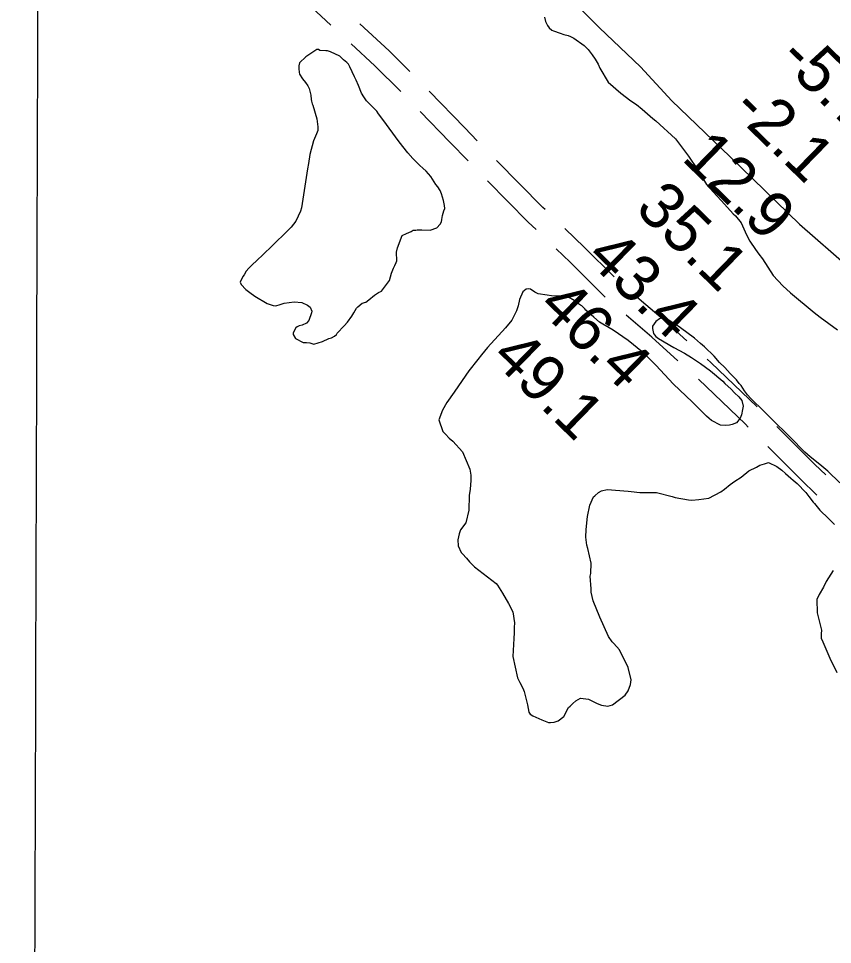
# Model space of a CAD drawing. Extents: x 3146026 to 3183936, y 897894 to 923344.
# Drawn here: x 3171140 to 3172319, y 911149 to 912491 of the extents above; entities that cross this region are included whole.
import ezdxf

# ---------------------------------------------------------------- set-up
doc = ezdxf.new("R2010")
doc.units = 0
for name, color, linetype in [('V-GRID-MAJR', 7, 'Continuous'), ('V-RIVR-EDGE', 7, 'Continuous'), ('V-RIVR-RANG', 7, 'Continuous'), ('V-ROAD-CNTR', 7, 'Continuous'), ('V-SITE-VEGE', 7, 'Continuous')]:
    doc.layers.add(name, color=color, linetype=linetype)

msp = doc.modelspace()

# ---------------------------------------------------------------- linework, layer by layer
at = {"layer": 'V-GRID-MAJR'}
msp.add_spline([(3171139.739, 903307.688), (3171158.249, 909367.4720000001), (3171176.767, 915430.341), (3171195.286, 921493.257), (3171195.295, 921496.294)], degree=3, dxfattribs=at)
at = {"layer": 'V-RIVR-EDGE'}
msp.add_lwpolyline([(3171909.7604397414, 912548.9168714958), (3171981.3681568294, 912477.7493021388), (3172040.717788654, 912421.2860583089), (3172086.204332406, 912371.9958038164), (3172170.4794758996, 912291.2786316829), (3172271.368358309, 912193.0701987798), (3172343.3932618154, 912130.2300927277)], dxfattribs=at)
at = {"layer": 'V-ROAD-CNTR'}
for points in [[(3171592.128481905, 912481.5951567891), (3171563.9692948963, 912507.5982092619), (3171517.5963283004, 912548.2484513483)], [(3171706.8015192, 912414.5415475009), (3171676.527957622, 912444.3772807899), (3171634.3485025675, 912483.4374600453)], [(3171693.725132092, 912385.3080883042), (3171655.8020423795, 912422.6827192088), (3171621.5019880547, 912454.4461990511)], [(3171804.355570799, 912314.137104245), (3171786.404285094, 912332.6700300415), (3171734.8438818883, 912386.0228365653)], [(3171791.0886884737, 912284.714632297), (3171764.8437149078, 912311.8099699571), (3171721.566935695, 912356.5911874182)], [(3171902.5150764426, 912214.3249582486), (3171899.1538444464, 912217.5401821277), (3171832.259361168, 912285.478653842)], [(3171889.552299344, 912185.2094897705), (3171878.0921555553, 912196.1718178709), (3171819.0612445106, 912256.1239945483)], [(3172002.8939126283, 912116.7504908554), (3171959.7979250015, 912159.5304118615), (3171931.4180597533, 912186.6774878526)], [(3171989.789089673, 912087.4880876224), (3171938.8600749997, 912138.0435881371), (3171918.4552912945, 912157.5620111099)], [(3172107.831524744, 912024.1596601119), (3172076.843093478, 912052.1194241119), (3172032.407737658, 912089.7984758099)], [(3172095.073270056, 911995.2646299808), (3172057.0889065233, 912029.5365758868), (3172019.8399865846, 912061.1218744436)], [(3172209.8377936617, 911928.3137008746), (3172142.7588854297, 911992.6459396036), (3172137.529803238, 911997.3639552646)], [(3172196.7876562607, 911899.1104547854), (3172192.7315462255, 911903.1526317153), (3172124.7028001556, 911968.3958154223)], [(3172309.255632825, 911829.749789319), (3172293.5084246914, 911845.075531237), (3172238.2415764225, 911900.1525328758)], [(3172296.2273357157, 911800.5668942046), (3172272.4575753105, 911823.7004687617), (3172225.1201789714, 911870.8752568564)]]:
    msp.add_lwpolyline(points, dxfattribs=at)
at = {"layer": 'V-SITE-VEGE'}
for points in [[(3171901.679000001, 912493.0919999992), (3171903.251000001, 912486.8459999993), (3171905.996000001, 912480.9879999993), (3171908.738000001, 912477.4779999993), (3171912.258000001, 912474.3569999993), (3171914.995000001, 912473.1919999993), (3171924.379000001, 912469.6919999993), (3171929.851000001, 912468.1369999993), (3171936.103000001, 912466.5869999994), (3171939.622000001, 912465.0279999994), (3171944.316000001, 912462.6939999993), (3171959.1780000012, 912452.1689999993), (3171965.052000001, 912446.3199999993), (3171970.923000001, 912438.5169999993), (3171975.230000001, 912432.2729999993), (3171979.541000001, 912424.8589999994), (3171981.895000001, 912419.0019999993), (3171994.041000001, 912398.7059999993), (3172012.430000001, 912383.1129999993), (3172026.906000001, 912371.8079999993), (3172035.118000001, 912366.3519999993), (3172043.335000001, 912359.7239999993), (3172058.594000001, 912346.4679999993), (3172062.897000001, 912342.9589999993), (3172091.463000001, 912316.8309999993), (3172110.259000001, 912291.4709999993), (3172123.184000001, 912272.3479999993), (3172136.504000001, 912250.8849999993), (3172138.853000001, 912247.7619999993), (3172141.594000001, 912245.0319999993), (3172151.379000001, 912234.1099999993), (3172158.424000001, 912227.0919999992), (3172175.254000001, 912208.3689999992)], [(3171688.738000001, 912158.8669999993), (3171695.349000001, 912176.8479999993), (3171701.984000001, 912179.5949999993), (3171708.622000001, 912182.7299999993), (3171711.354000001, 912184.2989999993), (3171715.259000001, 912184.6959999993), (3171717.213000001, 912185.0889999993), (3171724.244000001, 912185.1019999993), (3171735.967000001, 912184.3419999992), (3171745.727000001, 912187.8749999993), (3171750.796000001, 912193.3509999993), (3171752.353000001, 912196.4799999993), (3171753.129000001, 912199.9989999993), (3171753.901000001, 912205.8579999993), (3171755.842000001, 912212.5039999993), (3171757.399000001, 912216.0219999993), (3171757.002000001, 912220.3189999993), (3171755.427000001, 912227.3499999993), (3171752.674000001, 912237.1129999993), (3171750.712000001, 912241.7939999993), (3171747.188000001, 912247.2599999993), (3171744.445000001, 912250.7709999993), (3171741.705000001, 912254.6739999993), (3171739.354000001, 912258.5759999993), (3171737.005000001, 912262.0879999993), (3171730.349000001, 912269.8909999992), (3171725.262000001, 912274.1789999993), (3171720.959000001, 912278.0789999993), (3171710.782000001, 912288.2179999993), (3171703.737000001, 912296.4099999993), (3171691.210000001, 912312.4069999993), (3171667.711000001, 912344.7919999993), (3171661.444000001, 912352.9859999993), (3171658.702000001, 912356.8899999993), (3171643.831000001, 912371.7089999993), (3171639.915000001, 912377.5619999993), (3171636.782000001, 912383.0239999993), (3171632.076000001, 912393.9589999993), (3171628.934000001, 912401.7659999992), (3171626.583000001, 912406.4489999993), (3171619.915000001, 912421.2829999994), (3171617.566000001, 912425.1869999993), (3171615.217000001, 912427.5279999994), (3171610.523000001, 912431.4269999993), (3171605.042000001, 912436.4959999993), (3171591.7490000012, 912443.1129999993), (3171587.450000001, 912444.2759999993), (3171585.105000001, 912444.2739999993), (3171576.509000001, 912445.0419999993), (3171574.160000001, 912446.2089999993), (3171571.819000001, 912446.2049999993), (3171555.818000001, 912435.6309999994), (3171546.848000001, 912427.0199999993), (3171546.074000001, 912422.7209999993), (3171545.691000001, 912418.0309999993), (3171546.0900000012, 912413.3429999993), (3171546.875000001, 912410.6089999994), (3171551.186000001, 912403.9759999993), (3171555.493000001, 912398.5129999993), (3171559.017000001, 912393.4409999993), (3171560.977000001, 912389.5369999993), (3171563.339000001, 912380.1649999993), (3171563.738000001, 912373.9149999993), (3171564.133000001, 912371.1809999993), (3171565.313000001, 912367.6669999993), (3171566.097000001, 912365.7149999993), (3171571.991000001, 912345.7999999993), (3171573.575000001, 912334.0829999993), (3171573.194000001, 912329.0019999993), (3171571.639000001, 912323.9229999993), (3171566.968000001, 912314.1459999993), (3171561.924000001, 912294.2129999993), (3171559.992000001, 912280.9279999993), (3171558.444000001, 912273.1099999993), (3171549.945000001, 912216.8369999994), (3171548.390000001, 912212.1479999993), (3171541.384000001, 912197.2889999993), (3171534.757000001, 912188.6819999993), (3171522.665000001, 912176.9399999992), (3171514.475000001, 912169.1129999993), (3171506.2860000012, 912160.8939999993), (3171484.054000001, 912139.3699999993), (3171479.373000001, 912135.0629999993), (3171473.522000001, 912129.5839999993), (3171469.622000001, 912125.2799999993), (3171466.507000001, 912119.8049999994), (3171464.558000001, 912117.4559999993), (3171461.055000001, 912109.2479999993), (3171462.233000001, 912105.7329999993), (3171468.889000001, 912098.3219999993), (3171474.757000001, 912094.0329999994), (3171482.187000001, 912088.9689999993), (3171500.176000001, 912078.4499999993), (3171508.778000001, 912075.3389999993), (3171512.294000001, 912074.9539999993), (3171518.936000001, 912076.5289999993), (3171524.398000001, 912078.4929999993), (3171539.244000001, 912080.8629999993), (3171550.182000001, 912079.7099999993), (3171558.393000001, 912075.8159999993), (3171562.304000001, 912072.6969999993)], [(3172175.254000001, 912208.3689999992), (3172178.388000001, 912205.2479999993), (3172186.609000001, 912195.1039999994), (3172194.452000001, 912177.5359999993), (3172199.155000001, 912168.5599999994), (3172207.381000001, 912156.4619999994), (3172212.080000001, 912149.8309999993), (3172217.562000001, 912142.8059999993), (3172233.231000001, 912118.6109999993), (3172246.930000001, 912103.7879999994), (3172258.278000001, 912093.6499999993), (3172292.316000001, 912065.1889999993), (3172300.922000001, 912058.5619999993), (3172326.350000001, 912039.8529999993)], [(3171562.304000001, 912072.6969999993), (3171564.660000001, 912067.2309999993), (3171564.273000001, 912064.8859999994), (3171560.383000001, 912053.5499999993), (3171556.875000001, 912049.6389999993), (3171550.629000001, 912046.8919999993), (3171546.334000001, 912045.7129999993), (3171543.600000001, 912044.5349999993), (3171541.650000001, 912042.9699999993), (3171537.755000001, 912035.5399999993), (3171537.759000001, 912033.1949999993), (3171540.895000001, 912027.7309999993), (3171552.234000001, 912021.8899999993), (3171556.922000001, 912021.9009999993), (3171561.612000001, 912021.1259999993), (3171567.476000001, 912019.1829999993), (3171580.362000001, 912023.1109999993), (3171589.342000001, 912027.4239999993), (3171593.246000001, 912028.6039999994), (3171597.538000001, 912030.9549999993), (3171600.268000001, 912033.3039999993), (3171601.438000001, 912035.2579999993), (3171611.577000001, 912045.8249999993), (3171616.257000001, 912051.3039999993), (3171622.491000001, 912059.9089999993), (3171625.608000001, 912064.6029999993), (3171629.505000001, 912071.2529999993), (3171631.455000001, 912073.2069999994), (3171637.695000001, 912078.6879999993), (3171642.772000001, 912080.2559999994), (3171647.454000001, 912083.3939999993), (3171655.257000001, 912090.0479999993), (3171661.501000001, 912094.3569999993), (3171665.405000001, 912096.3169999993), (3171677.099000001, 912111.5719999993), (3171680.206000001, 912122.1279999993), (3171682.9280000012, 912129.5539999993), (3171684.875000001, 912133.0739999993), (3171686.821000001, 912137.7639999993), (3171687.597000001, 912140.1109999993), (3171687.185000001, 912152.6119999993), (3171688.738000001, 912158.8669999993)], [(3171905.496000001, 912090.5249999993), (3171892.602000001, 912092.0649999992), (3171887.910000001, 912094.7909999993), (3171881.651000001, 912099.0769999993), (3171878.526000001, 912099.4649999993), (3171875.009000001, 912099.0669999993), (3171870.328000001, 912095.1509999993), (3171865.660000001, 912084.2049999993), (3171863.719000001, 912074.8249999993), (3171860.9990000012, 912067.3989999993), (3171854.382000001, 912054.1029999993), (3171845.025000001, 912042.7569999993), (3171819.285000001, 912014.5829999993), (3171810.319000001, 912004.0199999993), (3171805.253000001, 911996.9789999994), (3171791.998000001, 911980.5469999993), (3171782.647000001, 911966.4669999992), (3171770.955000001, 911949.6469999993), (3171760.041000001, 911934.7829999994), (3171753.809000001, 911923.8319999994), (3171748.754000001, 911909.7579999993), (3171754.253000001, 911892.5799999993), (3171758.169000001, 911888.6779999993), (3171763.645000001, 911883.2179999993), (3171768.733000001, 911878.5389999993), (3171782.825000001, 911863.3259999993), (3171793.806000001, 911837.9509999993), (3171794.994000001, 911829.3599999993), (3171795.006000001, 911821.9359999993), (3171794.2490000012, 911809.0419999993), (3171792.700000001, 911800.0529999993), (3171792.346000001, 911778.5649999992), (3171787.691000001, 911760.5859999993), (3171780.285000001, 911750.0269999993), (3171778.342000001, 911744.5519999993), (3171776.011000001, 911735.5639999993), (3171776.808000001, 911726.9679999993), (3171781.123000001, 911717.6009999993), (3171783.081000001, 911715.2599999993), (3171788.559000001, 911709.4109999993), (3171793.257000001, 911703.9469999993), (3171800.3030000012, 911696.5369999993), (3171831.598000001, 911672.3679999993), (3171833.556000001, 911670.0279999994), (3171840.998000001, 911658.7099999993), (3171849.618000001, 911643.4899999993), (3171855.891000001, 911631.3879999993), (3171858.261000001, 911615.3749999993), (3171857.882000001, 911608.7329999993), (3171857.896000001, 911600.9199999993), (3171857.520000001, 911592.7139999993), (3171856.002000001, 911566.5359999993), (3171862.699000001, 911535.6829999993), (3171865.834000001, 911529.0469999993), (3171870.145000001, 911520.8489999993), (3171872.4990000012, 911515.7739999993), (3171877.219000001, 911496.6379999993), (3171879.191000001, 911486.0949999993), (3171881.149000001, 911482.9739999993), (3171885.061000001, 911480.6369999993), (3171897.963000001, 911474.7979999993), (3171907.737000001, 911471.2979999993), (3171910.473000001, 911471.3039999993), (3171915.941000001, 911471.7029999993), (3171921.798000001, 911473.2759999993), (3171929.992000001, 911479.5409999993), (3171936.609000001, 911492.8369999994), (3171938.950000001, 911494.7929999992), (3171942.852000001, 911498.7059999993), (3171947.142000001, 911502.2309999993), (3171950.654000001, 911504.1909999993), (3171953.780000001, 911506.1489999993), (3171965.500000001, 911504.9979999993), (3171968.236000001, 911503.4369999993), (3171978.012000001, 911498.7679999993), (3171984.268000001, 911496.0419999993), (3171993.646000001, 911494.8869999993), (3172000.284000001, 911496.8529999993), (3172018.623000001, 911510.5579999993), (3172022.910000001, 911516.8169999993), (3172026.410000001, 911526.1989999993), (3172027.180000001, 911532.8399999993), (3172022.850000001, 911550.8049999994), (3172010.304000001, 911576.1779999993), (3172002.086000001, 911585.5389999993), (3171999.737000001, 911587.8799999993), (3171994.643000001, 911595.6849999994), (3171981.702000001, 911623.7919999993), (3171972.287000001, 911647.2169999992), (3171969.140000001, 911660.1029999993), (3171969.131000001, 911664.7929999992), (3171967.927000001, 911683.1509999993), (3171968.701000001, 911687.0609999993), (3171969.457000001, 911701.9069999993), (3171964.7320000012, 911722.9949999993), (3171963.162000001, 911728.0719999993), (3171961.578000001, 911739.3999999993), (3171961.947000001, 911750.7289999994), (3171964.261000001, 911769.4869999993), (3171967.360000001, 911785.8969999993), (3171972.808000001, 911798.0189999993)], [(3172329.4650000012, 911818.5609999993), (3172312.245000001, 911835.3299999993), (3172300.508000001, 911845.0759999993), (3172286.813000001, 911855.9919999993), (3172278.990000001, 911863.0109999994), (3172257.4650000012, 911884.4609999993), (3172250.029000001, 911892.2619999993), (3172237.899000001, 911903.9599999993), (3172219.504000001, 911922.2919999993), (3172200.719000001, 911940.6219999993), (3172195.632000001, 911946.0819999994), (3172191.325000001, 911951.5439999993), (3172186.623000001, 911959.3509999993), (3172183.883000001, 911962.4699999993), (3172179.969000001, 911967.5429999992), (3172172.533000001, 911974.9519999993), (3172170.966000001, 911976.9039999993), (3172166.6610000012, 911981.1929999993), (3172163.136000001, 911985.4849999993), (3172155.311000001, 911992.8949999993), (3172147.4820000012, 912001.8649999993), (3172133.785000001, 912015.5189999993), (3172127.917000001, 912020.1949999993), (3172118.916000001, 912027.9929999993), (3172098.966000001, 912042.8049999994), (3172090.361000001, 912048.6499999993), (3172086.060000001, 912050.9859999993), (3172081.757000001, 912054.1029999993), (3172079.410000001, 912055.2729999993), (3172074.329000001, 912056.8249999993), (3172070.423000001, 912056.8209999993), (3172068.472000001, 912056.0349999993), (3172063.008000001, 912052.1189999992), (3172058.328000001, 912045.4689999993), (3172058.336000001, 912041.9529999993), (3172059.9110000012, 912034.9239999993), (3172061.089000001, 912032.5809999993), (3172063.045000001, 912030.6309999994), (3172066.956000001, 912027.5119999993), (3172089.2490000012, 912014.6589999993), (3172104.498000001, 912006.0899999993), (3172114.668000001, 911999.8559999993), (3172127.966000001, 911991.2829999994), (3172142.439000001, 911980.7599999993), (3172160.046000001, 911965.5539999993), (3172163.179000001, 911962.4349999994), (3172172.176000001, 911954.2469999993), (3172177.266000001, 911948.7849999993), (3172183.526000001, 911942.9359999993), (3172187.442000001, 911937.8629999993), (3172189.410000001, 911929.2719999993), (3172188.636000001, 911924.5839999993), (3172187.088000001, 911916.7669999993), (3172185.142000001, 911912.0749999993), (3172180.075000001, 911905.4249999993), (3172173.827000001, 911903.0699999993), (3172169.924000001, 911901.8919999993), (3172163.282000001, 911901.4879999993), (3172156.640000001, 911901.8669999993), (3172143.734000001, 911908.8779999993), (3172140.213000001, 911911.6079999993), (3172136.693000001, 911914.7269999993), (3172128.474000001, 911923.3079999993), (3172115.953000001, 911935.0059999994), (3172088.167000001, 911961.9149999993), (3172063.507000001, 911988.4379999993), (3172051.375000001, 912000.5299999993), (3172043.941000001, 912007.5479999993), (3172022.816000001, 912024.6999999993), (3172001.301000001, 912039.5089999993), (3171995.436000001, 912043.0159999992), (3171986.050000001, 912048.0779999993), (3171981.358000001, 912051.1969999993), (3171973.141000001, 912058.2159999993), (3171961.793000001, 912068.3529999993), (3171960.227000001, 912070.3029999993), (3171955.922000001, 912074.5939999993), (3171953.966000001, 912075.7629999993), (3171949.6610000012, 912078.8799999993), (3171946.925000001, 912081.2209999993), (3171944.578000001, 912082.3879999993), (3171936.757000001, 912087.4529999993), (3171930.502000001, 912089.7859999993), (3171926.986000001, 912089.3899999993), (3171918.392000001, 912088.9849999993), (3171912.142000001, 912089.3639999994), (3171905.496000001, 912090.5249999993)], [(3171972.808000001, 911798.0189999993), (3171974.759000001, 911799.5879999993), (3171980.219000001, 911804.2839999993), (3171984.123000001, 911806.6349999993), (3171992.714000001, 911808.6029999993), (3172022.801000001, 911806.3119999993), (3172027.098000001, 911805.9269999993), (3172039.994000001, 911804.3869999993), (3172064.216000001, 911804.4299999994), (3172086.885000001, 911798.6069999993), (3172091.186000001, 911797.0509999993), (3172110.335000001, 911793.5689999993), (3172115.025000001, 911793.1859999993), (3172125.570000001, 911793.9869999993), (3172139.632000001, 911796.3539999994), (3172157.197000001, 911805.3739999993), (3172162.659000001, 911809.2879999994), (3172170.853000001, 911815.9409999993), (3172177.487000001, 911820.6419999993), (3172186.852000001, 911826.5169999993), (3172197.776000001, 911835.5219999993), (3172208.704000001, 911841.0109999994), (3172213.779000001, 911843.7549999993), (3172220.417000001, 911846.1109999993), (3172226.274000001, 911847.6829999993), (3172238.396000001, 911841.8449999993), (3172245.437000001, 911836.7779999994), (3172250.916000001, 911831.7089999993), (3172258.739000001, 911825.0799999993), (3172262.262000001, 911822.3519999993), (3172267.738000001, 911817.2829999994), (3172280.264000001, 911804.4109999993), (3172284.962000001, 911798.5579999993), (3172290.835000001, 911790.3639999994), (3172292.793000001, 911788.4139999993), (3172300.623000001, 911778.6619999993), (3172302.972000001, 911776.3209999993), (3172310.797000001, 911769.3019999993), (3172322.145000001, 911757.9909999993)], [(3172319.917000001, 911691.1809999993), (3172309.788000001, 911675.5369999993), (3172305.8940000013, 911667.3259999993), (3172299.662000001, 911656.3759999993), (3172296.549000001, 911649.3389999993), (3172296.582000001, 911630.1939999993), (3172302.876000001, 911604.8109999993), (3172302.495000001, 911599.3429999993), (3172302.507000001, 911593.0899999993), (3172304.858000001, 911588.0149999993), (3172315.057000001, 911564.2009999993), (3172325.250000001, 911543.5119999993)]]:
    msp.add_lwpolyline(points, dxfattribs=at)

# ---------------------------------------------------------------- texts
at = {"layer": 'V-RIVR-RANG'}
for s, p in [('-5.7', (3172238.3086033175, 912430.6574873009)), ('-2.1', (3172170.4326451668, 912357.1754657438)), ('12.9', (3172098.965598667, 912287.188489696)), ('35.1', (3172031.278645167, 912213.5214657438)), ('43.4', (3171960.0016033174, 912143.3514873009)), ('46.4', (3171890.4246033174, 912071.5244873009)), ('49.1', (3171822.548645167, 911998.0424657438))]:
    msp.add_text(s, height=66.99999999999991, rotation=315.7683257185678, dxfattribs=at).set_placement(p)

doc.saveas('drawing.dxf')
